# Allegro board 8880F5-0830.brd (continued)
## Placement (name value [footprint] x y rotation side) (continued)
NOREF#872  -  []  302.11 192.14 0 top
NOREF#873  -  []  166.06 175.58 90 top
NOREF#874  -  []  337.9 246.99 0 top
NOREF#875  -  []  210.86 242.18 90 top
NOREF#876  -  []  292.74 288.86 0 top
NOREF#877  -  []  215.96 248.49 0 top
NOREF#878  -  []  296.96 240.71 0 top
NOREF#879  -  []  240.83 194.63 0 top
NOREF#880  -  []  378.33 257.11 90 top
NOREF#881  -  []  300.36 237.06 0 top
NOREF#882  -  []  263.31 164.72 0 top
NOREF#883  -  []  313.94 286.96 90 top
NOREF#884  -  []  314.71 129.74 90 top
NOREF#885  -  []  209.23 191.22 90 top
NOREF#886  -  []  94.93 190.55 0 top
NOREF#887  -  []  218.16 237.06 0 top
NOREF#888  -  []  352.25 241.05 90 top
NOREF#889  -  []  412.37 265.37 0 top
NOREF#890  -  []  167.7 241.43 90 top
NOREF#891  -  []  230.43 254.01 0 top
NOREF#892  -  []  201.23 192.32 90 top
NOREF#893  -  []  209.08 256.4 90 top
NOREF#894  -  []  221.56 190.49 0 top
NOREF#895  -  []  462.06 291.28 90 top
NOREF#896  -  []  201.49 165.4 90 top
NOREF#897  -  []  209.49 162.1 90 top
NOREF#898  -  []  405.93 272.56 90 top
NOREF#899  -  []  303.84 288.86 0 top
NOREF#900  -  []  167.7 214 0 top
NOREF#901  -  []  231.15 219.63 90 top
NOREF#902  -  []  310.43 188.88 0 top
NOREF#903  -  []  397.8 163.19 90 top
NOREF#904  -  []  309.21 193.37 0 top
NOREF#905  -  []  121.9 231.22 0 top
NOREF#906  -  []  309.05 211.67 0 top
NOREF#907  -  []  310.43 253.37 90 top
NOREF#908  -  []  199.33 212.85 0 top
NOREF#909  -  []  394 217.36 0 top
NOREF#910  -  []  182.82 175.58 90 top
NOREF#911  -  []  306.83 209.63 90 top
NOREF#912  -  []  334.29 265.56 0 top
NOREF#913  -  []  339.33 265.56 0 top
NOREF#914  -  []  390.53 188.15 0 top
NOREF#915  -  []  201.49 173.11 90 top
NOREF#916  -  []  319.33 176.03 0 top
NOREF#917  -  []  392.04 241.11 90 top
NOREF#918  -  []  273.95 147.38 90 top
NOREF#919  -  []  312.79 288.86 90 top
NOREF#920  -  []  119.7 231.22 0 top
NOREF#921  -  []  310.43 246.34 90 top
NOREF#922  -  []  330.51 288.86 0 top
NOREF#923  -  []  412.36 209.61 90 top
NOREF#924  -  []  122.19 214.79 0 top
NOREF#925  -  []  398.65 225.11 0 top
NOREF#926  -  []  369.38 257.11 0 top
NOREF#927  -  []  177.33 187.32 90 top
NOREF#928  -  []  108.01 195.15 0 top
NOREF#929  -  []  410.78 131.89 0 top
NOREF#930  -  []  330.73 204.35 90 top
NOREF#931  -  []  118.45 234.24 90 top
NOREF#932  -  []  304.65 211.67 0 top
NOREF#933  -  []  263.71 288.86 0 top
NOREF#934  -  []  408.37 258.64 90 top
NOREF#935  -  []  175.7 148.38 90 top
NOREF#936  -  []  262.36 223.82 90 top
NOREF#937  -  []  230.41 187.61 90 top
NOREF#938  -  []  247.57 205.86 90 top
NOREF#939  -  []  184.47 200.54 90 top
NOREF#940  -  []  211.11 173.86 90 top
NOREF#941  -  []  272.25 189.82 0 top
NOREF#942  -  []  128.21 178.64 0 top
NOREF#943  -  []  406.65 223.21 90 top
NOREF#944  -  []  273.09 288.41 90 top
NOREF#945  -  []  263.63 225.04 90 top
NOREF#946  -  []  296.81 275.94 0 top
NOREF#947  -  []  229.51 247.93 0 top
NOREF#948  -  []  108.01 222.33 0 top
NOREF#949  -  []  167.7 260.9 90 top
NOREF#950  -  []  400.24 198.08 90 top
NOREF#951  -  []  463.61 214.96 0 top
NOREF#952  -  []  167.7 159.65 0 top
NOREF#953  -  []  272.55 243.91 0 top
NOREF#954  -  []  326.17 131.69 90 top
NOREF#955  -  []  93.76 271.33 90 top
NOREF#956  -  []  259.65 204.65 90 top
NOREF#957  -  []  456.08 214.96 0 top
NOREF#958  -  []  449.99 174.46 0 top
NOREF#959  -  []  200.98 260.9 90 top
NOREF#960  -  []  167.7 247.18 90 top
NOREF#961  -  []  385.19 297.12 0 top
NOREF#962  -  []  311.15 219.63 90 top
NOREF#963  -  []  383.09 224.85 0 top
NOREF#964  -  []  167.7 173.11 0 top
NOREF#965  -  []  338.2 186.67 0 top
NOREF#966  -  []  211.11 146.93 90 top
NOREF#967  -  []  108.27 171.02 0 top
NOREF#968  -  []  253.4 265.56 0 top
NOREF#969  -  []  415.08 139.89 0 top
NOREF#970  -  []  334.29 265.56 90 top
NOREF#971  -  []  473.6 162.62 90 top
NOREF#972  -  []  200.98 255.15 90 top
NOREF#973  -  []  254.61 264.65 90 top
NOREF#974  -  []  302.49 296.86 0 top
NOREF#975  -  []  368.03 249.11 0 top
NOREF#976  -  []  175.8 201.79 90 top
NOREF#977  -  []  338.36 288.91 90 top
NOREF#978  -  []  310.43 186.34 90 top
NOREF#979  -  []  465.31 186.77 0 top
NOREF#980  -  []  308.36 262.16 45 top
NOREF#981  -  []  408.28 129.99 0 top
NOREF#982  -  []  230.73 187.93 0 top
NOREF#983  -  []  165.8 131.57 0 top
NOREF#984  -  []  309.51 243.41 0 top
NOREF#985  -  []  322.62 139.64 0 top
NOREF#986  -  []  122.19 247.3 90 top
NOREF#987  -  []  199.33 199.39 90 top
NOREF#988  -  []  295.96 248.49 0 top
NOREF#989  -  []  184.47 260.9 90 top
NOREF#990  -  []  419.22 257.37 90 top
NOREF#991  -  []  331.62 204.35 90 top
NOREF#992  -  []  354.08 286.96 90 top
NOREF#993  -  []  217.83 234.63 90 top
NOREF#994  -  []  272.24 181.05 90 top
NOREF#995  -  []  201.23 215.35 90 top
NOREF#996  -  []  381.74 281.11 0 top
NOREF#997  -  []  271.04 244.23 0 top
NOREF#998  -  []  246.23 173.13 0 top
NOREF#999  -  []  256.77 223.82 90 top
NOREF#1000  -  []  175.7 264.1 90 top
NOREF#1001  -  []  339.89 288.41 90 top
NOREF#1002  -  []  369.63 289.12 0 top
NOREF#1003  -  []  330.17 165.04 90 top
NOREF#1004  -  []  369.38 257.11 0 top
NOREF#1005  -  []  419.64 256.82 90 top
NOREF#1006  -  []  258.2 246.67 0 top
NOREF#1007  -  []  235.85 296.61 0 top
NOREF#1008  -  []  310.43 247.61 0 top
NOREF#1009  -  []  396.03 146.88 0 top
NOREF#1010  -  []  312.25 211.67 90 top
NOREF#1011  -  []  450.03 210.36 0 top
NOREF#1012  -  []  409.74 180.2 90 top
NOREF#1013  -  []  277.17 288.86 0 top
NOREF#1014  -  []  410.52 289.12 0 top
NOREF#1015  -  []  333.72 264.65 90 top
NOREF#1016  -  []  301.56 242.89 0 top
NOREF#1017  -  []  201.23 241.43 90 top
NOREF#1018  -  []  420.37 255.47 90 top
NOREF#1019  -  []  383.73 202.38 90 top
NOREF#1020  -  []  262.36 225.04 90 top
NOREF#1021  -  []  168.13 172.56 90 top
NOREF#1022  -  []  346.27 129.42 0 top
NOREF#1023  -  []  271.04 185.5 0 top
NOREF#1024  -  []  304.65 271.67 0 top
NOREF#1025  -  []  240.94 211.63 90 top
NOREF#1026  -  []  310.73 193.69 0 top
NOREF#1027  -  []  343.95 163.52 90 top
NOREF#1028  -  []  165.8 226.57 90 top
NOREF#1029  -  []  518.38 273.87 90 top
NOREF#1030  -  []  395.2 281.11 0 top
NOREF#1031  -  []  479.44 195.66 0 top
NOREF#1032  -  []  451.68 186.77 0 top
NOREF#1033  -  []  463.11 230.2 0 top
NOREF#1034  -  []  473.79 196.21 0 top
NOREF#1035  -  []  119.95 222.33 0 top
NOREF#1036  -  []  271.34 243.91 0 top
NOREF#1037  -  []  351.04 189.18 0 top
NOREF#1038  -  []  343.31 224.74 0 top
NOREF#1039  -  []  209.23 243.88 90 top
NOREF#1040  -  []  201.49 146.18 90 top
NOREF#1041  -  []  250.74 164.74 0 top
NOREF#1042  -  []  461.96 210.36 0 top
NOREF#1043  -  []  184.47 242.78 90 top
NOREF#1044  -  []  371.48 257.11 0 top
NOREF#1045  -  []  332.83 204.65 90 top
NOREF#1046  -  []  306.71 139.64 0 top
NOREF#1047  -  []  304.61 131.64 0 top
NOREF#1048  -  []  351.34 249.5 0 top
NOREF#1049  -  []  331.22 253.63 0 top
NOREF#1050  -  []  184.47 260.9 90 top
NOREF#1051  -  []  397.38 163.64 90 top
NOREF#1052  -  []  309.21 253.37 0 top
NOREF#1053  -  []  271.34 249.5 0 top
NOREF#1054  -  []  250.73 204.35 90 top
NOREF#1055  -  []  459.28 236.14 90 top
NOREF#1056  -  []  297.83 174.63 90 top
NOREF#1057  -  []  369.63 273.11 0 top
NOREF#1058  -  []  327.57 205.86 90 top
NOREF#1059  -  []  184.47 241.43 90 top
NOREF#1060  -  []  330.73 205.56 90 top
NOREF#1061  -  []  247.25 205.56 0 top
NOREF#1062  -  []  383.09 257.11 0 top
NOREF#1063  -  []  263.31 224.72 0 top
NOREF#1064  -  []  387.8 210.63 90 top
NOREF#1065  -  []  340.83 174.63 90 top
NOREF#1066  -  []  250.18 242.88 0 top
NOREF#1067  -  []  272.25 182.96 0 top
NOREF#1068  -  []  230.73 253.69 0 top
NOREF#1069  -  []  310.73 189.2 0 top
NOREF#1070  -  []  320.83 194.63 0 top
NOREF#1071  -  []  328.62 290.13 90 top
NOREF#1072  -  []  461.96 174.55 0 top
NOREF#1073  -  []  408.88 133.16 90 top
NOREF#1074  -  []  401.87 194.18 90 top
NOREF#1075  -  []  100.98 195.15 0 top
NOREF#1076  -  []  387.08 171.64 0 top
NOREF#1077  -  []  331.38 164.74 90 top
NOREF#1078  -  []  230.43 189.52 0 top
NOREF#1079  -  []  413.75 171.64 0 top
NOREF#1080  -  []  118.99 166.5 90 top
NOREF#1081  -  []  396.03 163.64 0 top
NOREF#1082  -  []  351.34 243.91 0 top
NOREF#1083  -  []  272.25 245.5 0 top
NOREF#1084  -  []  418.12 289.12 0 top
NOREF#1085  -  []  339.65 204.65 90 top
NOREF#1086  -  []  261.16 135.74 90 top
NOREF#1087  -  []  422.95 163.69 90 top
NOREF#1088  -  []  167.7 176.66 90 top
NOREF#1089  -  []  330.17 225.04 90 top
NOREF#1090  -  []  453.88 239.34 0 top
NOREF#1091  -  []  379.52 171.39 0 top
NOREF#1092  -  []  331.05 204.65 90 top
NOREF#1093  -  []  215.96 237.06 0 top
NOREF#1094  -  []  405.93 240.66 90 top
NOREF#1095  -  []  314.55 286.96 0 top
NOREF#1096  -  []  352.25 185.5 0 top
NOREF#1097  -  []  259.88 288.41 90 top
NOREF#1098  -  []  376.15 192.88 90 top
NOREF#1099  -  []  379.48 255.21 90 top
NOREF#1100  -  []  119.95 187.53 0 top
NOREF#1101  -  []  184.47 165.4 90 top
NOREF#1102  -  []  242.23 173.13 90 top
NOREF#1103  -  []  376.98 241.11 0 top
NOREF#1104  -  []  351.04 245.5 0 top
NOREF#1105  -  []  192.57 228.97 90 top
NOREF#1106  -  []  311.15 159.63 90 top
NOREF#1107  -  []  336.77 223.82 90 top
NOREF#1108  -  []  351.04 185.5 0 top
NOREF#1109  -  []  230.43 248.88 90 top
NOREF#1110  -  []  410.27 257.37 0 top
NOREF#1111  -  []  201.49 146.18 0 top
NOREF#1112  -  []  168.69 292.55 90 top
NOREF#1113  -  []  106.76 210.11 90 top
NOREF#1114  -  []  396.55 257.37 0 top
NOREF#1115  -  []  300.36 188.49 0 top
NOREF#1116  -  []  331.62 265.56 0 top
NOREF#1117  -  []  201.23 244.98 90 top
NOREF#1118  -  []  385.93 161.74 0 top
NOREF#1119  -  []  333.33 241.33 90 top
NOREF#1120  -  []  310.73 187.93 0 top
NOREF#1121  -  []  209.33 187.82 90 top
NOREF#1122  -  []  410.84 180.15 90 top
NOREF#1123  -  []  310.73 253.69 0 top
NOREF#1124  -  []  385.19 232.85 0 top
NOREF#1125  -  []  387.08 154.88 0 top
NOREF#1126  -  []  229.21 248.88 0 top
NOREF#1127  -  []  230.73 189.2 0 top
NOREF#1128  -  []  251.06 225.04 90 top
NOREF#1129  -  []  275.3 155.38 0 top
NOREF#1130  -  []  471.21 168.33 90 top
NOREF#1131  -  []  485.36 259.9 90 top
NOREF#1132  -  []  419.65 256.92 90 top
NOREF#1133  -  []  252.83 265.86 90 top
NOREF#1134  -  []  284.77 288.86 0 top
NOREF#1135  -  []  390.53 163.64 0 top
NOREF#1136  -  []  333.4 205.55 0 top
NOREF#1137  -  []  369.38 241.11 0 top
NOREF#1138  -  []  259.45 288.86 90 top
NOREF#1139  -  []  415.61 179.97 90 top
NOREF#1140  -  []  379.73 271.21 90 top
NOREF#1141  -  []  271.56 134.74 90 top
NOREF#1142  -  []  165.8 185.42 90 top
NOREF#1143  -  []  343.98 288.86 0 top
NOREF#1144  -  []  232.25 211.67 90 top
NOREF#1145  -  []  259.88 288.31 90 top
NOREF#1146  -  []  303.84 288.86 0 top
NOREF#1147  -  []  400.91 207.71 0 top
NOREF#1148  -  []  352.24 243.59 90 top
NOREF#1149  -  []  302.11 129.74 0 top
NOREF#1150  -  []  315.16 290.13 90 top
NOREF#1151  -  []  327.7 131.19 90 top
NOREF#1152  -  []  167.7 204.09 90 top
NOREF#1153  -  []  406.65 287.22 90 top
NOREF#1154  -  []  36.1 129.71 90 top
NOREF#1155  -  []  398.65 289.12 0 top
NOREF#1156  -  []  406.94 131.34 90 top
NOREF#1157  -  []  371.73 297.12 0 top
NOREF#1158  -  []  175.7 141.67 90 top
NOREF#1159  -  []  392.47 288.67 90 top
NOREF#1160  -  []  200.98 260.9 90 top
NOREF#1161  -  []  471.21 219.38 0 top
NOREF#1162  -  []  295.19 271.65 90 top
NOREF#1163  -  []  398.65 273.11 0 top
NOREF#1164  -  []  331.62 205.55 0 top
NOREF#1165  -  []  312.21 131.64 0 top
NOREF#1166  -  []  319.33 183.63 90 top
NOREF#1167  -  []  418.38 131.89 0 top
NOREF#1168  -  []  272.25 241.05 90 top
NOREF#1169  -  []  264.29 280.1 0 top
NOREF#1170  -  []  230.73 183.41 0 top
NOREF#1171  -  []  301.56 179.06 0 top
NOREF#1172  -  []  408.63 290.39 90 top
NOREF#1173  -  []  249.6 223.52 90 top
NOREF#1174  -  []  201.21 276.04 90 top
NOREF#1175  -  []  184.47 219.75 90 top
NOREF#1176  -  []  472.86 174.55 90 top
NOREF#1177  -  []  451.68 239.34 0 top
NOREF#1178  -  []  259.33 205.55 0 top
NOREF#1179  -  []  409.43 139.89 0 top
NOREF#1180  -  []  200.98 255.15 0 top
NOREF#1181  -  []  167.7 233.47 90 top
NOREF#1182  -  []  120.24 171.1 0 top
NOREF#1183  -  []  115.61 219.13 90 top
NOREF#1184  -  []  396.28 146.93 90 top
NOREF#1185  -  []  242.23 233.13 0 top
NOREF#1186  -  []  167.7 247.18 90 top
NOREF#1187  -  []  310.43 246.34 0 top
NOREF#1188  -  []  376.23 209.11 0 top
NOREF#1189  -  []  393.19 271.21 90 top
NOREF#1190  -  []  249.13 140.14 0 top
NOREF#1191  -  []  330.49 163.52 90 top
NOREF#1192  -  []  167.7 132.72 90 top
NOREF#1193  -  []  182.82 216.47 90 top
NOREF#1194  -  []  248.61 290.13 90 top
NOREF#1195  -  []  230.41 253.37 90 top
NOREF#1196  -  []  331.38 224.74 90 top
NOREF#1197  -  []  175.7 216.45 90 top
NOREF#1198  -  []  223.56 185.29 90 top
NOREF#1199  -  []  352.25 182.32 90 top
NOREF#1200  -  []  253.4 205.55 0 top
NOREF#1201  -  []  295.96 177.06 0 top
NOREF#1202  -  []  110.21 195.15 0 top
NOREF#1203  -  []  118.7 190.55 90 top
NOREF#1204  -  []  475.04 239.09 0 top
NOREF#1205  -  []  216.96 180.71 0 top
NOREF#1206  -  []  343.31 164.74 0 top
NOREF#1207  -  []  250.73 265.56 0 top
NOREF#1208  -  []  390.53 146.88 0 top
NOREF#1209  -  []  167.7 219.75 90 top
NOREF#1210  -  []  201.21 273.5 90 top
NOREF#1211  -  []  177.33 160.4 90 top
NOREF#1212  -  []  456.08 230.2 0 top
NOREF#1213  -  []  118.96 179.19 0 top
NOREF#1214  -  []  397.57 131.89 0 top
NOREF#1215  -  []  390.53 180.15 0 top
NOREF#1216  -  []  328.42 129.74 90 top
NOREF#1217  -  []  396.55 289.12 0 top
NOREF#1218  -  []  250.73 265.55 0 top
NOREF#1219  -  []  262.04 224.74 0 top
NOREF#1220  -  []  352.24 183.59 90 top
NOREF#1221  -  []  184.47 229.07 90 top
NOREF#1222  -  []  116.27 178.64 0 top
NOREF#1223  -  []  318.32 131.64 0 top
NOREF#1224  -  []  201.49 178.86 90 top
NOREF#1225  -  []  313.22 288.41 90 top
NOREF#1226  -  []  254.29 264.35 90 top
NOREF#1227  -  []  277.5 155.38 0 top
NOREF#1228  -  []  407.77 255.47 0 top
NOREF#1229  -  []  353.35 288.41 90 top
NOREF#1230  -  []  256.77 225.04 90 top
NOREF#1231  -  []  303.15 211.32 90 top
NOREF#1232  -  []  223.56 173.86 90 top
NOREF#1233  -  []  401.89 180.15 0 top
NOREF#1234  -  []  167.7 173.11 90 top
NOREF#1235  -  []  352.25 249.82 0 top
NOREF#1236  -  []  251.62 265.56 90 top
NOREF#1237  -  []  251.62 204.35 90 top
NOREF#1238  -  []  317.66 164.74 0 top
NOREF#1239  -  []  251.54 192.73 90 top
NOREF#1240  -  []  309.51 247.93 0 top
NOREF#1241  -  []  192.47 218.65 90 top
NOREF#1242  -  []  459.28 168.33 90 top
NOREF#1243  -  []  175.7 230.17 90 top
NOREF#1244  -  []  272.55 241.37 0 top
NOREF#1245  -  []  385.32 178.25 90 top
NOREF#1246  -  []  403.41 209.61 0 top
NOREF#1247  -  []  384.59 179.6 90 top
NOREF#1248  -  []  118.96 174.04 90 top
NOREF#1249  -  []  511.59 259.9 90 top
NOREF#1250  -  []  184.47 241.43 0 top
NOREF#1251  -  []  546.67 300.44 90 top
NOREF#1252  -  []  333.72 265.86 90 top
NOREF#1253  -  []  373.87 188.15 0 top
NOREF#1254  -  []  290.11 280.1 0 top
NOREF#1255  -  []  106.76 222.88 0 top
NOREF#1256  -  []  381.86 129.99 0 top
NOREF#1257  -  []  475.36 127 90 top
NOREF#1258  -  []  423.45 146.93 90 top
NOREF#1259  -  []  272.55 182.64 0 top
NOREF#1260  -  []  396.55 225.11 0 top
NOREF#1261  -  []  260.74 143.19 0 top
NOREF#1262  -  []  395.07 129.99 0 top
NOREF#1263  -  []  273.95 155.38 0 top
NOREF#1264  -  []  184.47 256.5 90 top
NOREF#1265  -  []  230.43 253.37 90 top
NOREF#1266  -  []  471.21 175.95 0 top
NOREF#1267  -  []  247.57 204.65 90 top
NOREF#1268  -  []  299.59 288.86 90 top
NOREF#1269  -  []  331.06 165.04 90 top
NOREF#1270  -  []  246.23 233.13 0 top
NOREF#1271  -  []  418.63 131.94 90 top
NOREF#1272  -  []  292.74 296.86 0 top
NOREF#1273  -  []  351.04 242.96 0 top
NOREF#1274  -  []  304.61 131.64 0 top
NOREF#1275  -  []  192.47 177.76 90 top
NOREF#1276  -  []  419.4 171.64 0 top
NOREF#1277  -  []  459.28 183.57 90 top
NOREF#1278  -  []  332.83 205.86 90 top
NOREF#1279  -  []  319.33 176.03 90 top
NOREF#1280  -  []  330.49 223.52 90 top
NOREF#1281  -  []  239.33 183.63 90 top
NOREF#1282  -  []  261.82 290.13 90 top
NOREF#1283  -  []  272.55 185.18 0 top
NOREF#1284  -  []  225.83 264.31 0 top
NOREF#1285  -  []  165.8 254 90 top
NOREF#1286  -  []  192.47 236.67 90 top
NOREF#1287  -  []  112.41 195.15 0 top
NOREF#1288  -  []  367.48 258.38 90 top
NOREF#1289  -  []  306.27 216.63 90 top
NOREF#1290  -  []  182.82 162.12 90 top
NOREF#1291  -  []  308.36 202.16 45 top
NOREF#1292  -  []  367.48 225.87 90 top
NOREF#1293  -  []  375.22 180.15 0 top
NOREF#1294  -  []  368.28 281.11 0 top
NOREF#1295  -  []  461.86 187.32 0 top
NOREF#1296  -  []  300.11 273.24 90 top
NOREF#1297  -  []  240.83 254.63 0 top
NOREF#1298  -  []  208.98 259.8 90 top
NOREF#1299  -  []  276.4 147.38 0 top
NOREF#1300  -  []  122.15 195.15 0 top
NOREF#1301  -  []  201.49 151.93 90 top
NOREF#1302  -  []  366.88 255.21 0 top
NOREF#1303  -  []  251.38 164.74 90 top
NOREF#1304  -  []  122.15 222.33 0 top
NOREF#1305  -  []  270.04 135.24 90 top
NOREF#1306  -  []  409.17 281.37 0 top
NOREF#1307  -  []  411.01 209.61 0 top
NOREF#1308  -  []  201.23 200.54 0 top
NOREF#1309  -  []  403.99 171.64 0 top
NOREF#1310  -  []  467.51 186.77 0 top
NOREF#1311  -  []  346.27 130.77 90 top
NOREF#1312  -  []  165.8 240.28 90 top
NOREF#1313  -  []  309.12 154.05 0 top
NOREF#1314  -  []  209.23 250.38 90 top
NOREF#1315  -  []  371.48 249.11 0 top
NOREF#1316  -  []  341.48 286.96 0 top
NOREF#1317  -  []  184.47 214 0 top
NOREF#1318  -  []  230.41 193.37 90 top
NOREF#1319  -  []  339.65 264.65 90 top
NOREF#1320  -  []  305.83 204.31 0 top
NOREF#1321  -  []  386.53 164.91 90 top
NOREF#1322  -  []  184.47 147.28 90 top
NOREF#1323  -  []  119.7 238.84 0 top
NOREF#1324  -  []  248.21 132.69 90 top
NOREF#1325  -  []  403.99 163.64 0 top
NOREF#1326  -  []  352.25 182.96 0 top
NOREF#1327  -  []  351.34 185.18 0 top
NOREF#1328  -  []  397.3 209.36 0 top
NOREF#1329  -  []  309.21 186.34 0 top
NOREF#1330  -  []  263.2 172.26 90 top
NOREF#1331  -  []  236.27 289.16 90 top
NOREF#1332  -  []  396.55 289.12 0 top
NOREF#1333  -  []  251.22 253.63 0 top
NOREF#1334  -  []  354.27 131.87 90 top
NOREF#1335  -  []  247.25 265.56 90 top
NOREF#1336  -  []  263.95 163.52 90 top
NOREF#1337  -  []  309.21 248.88 0 top
NOREF#1338  -  []  259.33 264.35 90 top
NOREF#1339  -  []  251.86 192.43 90 top
NOREF#1340  -  []  263.14 270.2 90 top
NOREF#1341  -  []  352.25 245.5 0 top
NOREF#1342  -  []  230.43 248.88 90 top
NOREF#1343  -  []  312.25 271.67 90 top
NOREF#1344  -  []  226.83 209.63 90 top
NOREF#1345  -  []  106.11 234.24 0 top
NOREF#1346  -  []  118.7 195.7 0 top
NOREF#1347  -  []  215.96 177.06 0 top
NOREF#1348  -  []  275.28 290.13 90 top
NOREF#1349  -  []  290.11 280.1 0 top
NOREF#1350  -  []  396.55 273.11 0 top
NOREF#1351  -  []  449.99 174.46 0 top
NOREF#1352  -  []  327.15 286.96 90 top
NOREF#1353  -  []  317.05 288.86 0 top
NOREF#1354  -  []  259.33 205.56 0 top
NOREF#1355  -  []  272.24 183.59 90 top
NOREF#1356  -  []  394.66 258.64 90 top
NOREF#1357  -  []  343.63 223.82 90 top
NOREF#1358  -  []  317.83 197.63 0 top
NOREF#1359  -  []  98.78 195.15 0 top
NOREF#1360  -  []  317.66 164.72 0 top
NOREF#1361  -  []  471.21 168.33 0 top
NOREF#1362  -  []  315.7 296.86 0 top
NOREF#1363  -  []  404.15 273.11 0 top
NOREF#1364  -  []  251.38 223.52 90 top
NOREF#1365  -  []  192.47 246.08 90 top
NOREF#1366  -  []  219.81 213.69 90 top
NOREF#1367  -  []  332.61 288.86 0 top
NOREF#1368  -  []  423.2 146.88 0 top
NOREF#1369  -  []  242.23 173.13 0 top
NOREF#1370  -  []  230.73 193.69 0 top
NOREF#1371  -  []  272.25 183.59 90 top
NOREF#1372  -  []  106.76 215.26 0 top
NOREF#1373  -  []  230.41 186.34 90 top
NOREF#1374  -  []  209.49 175.56 90 top
NOREF#1375  -  []  383.09 241.11 0 top
NOREF#1376  -  []  342.08 290.13 90 top
NOREF#1377  -  []  333.4 264.35 90 top
NOREF#1378  -  []  108.01 214.71 0 top
NOREF#1379  -  []  184.47 217.55 90 top
NOREF#1380  -  []  112.41 222.33 0 top
NOREF#1381  -  []  329.6 223.52 90 top
NOREF#1382  -  []  220.36 237.06 0 top
NOREF#1383  -  []  388.43 180.15 0 top
NOREF#1384  -  []  192.47 250.38 90 top
NOREF#1385  -  []  385.36 194.18 90 top
NOREF#1386  -  []  247.25 205.55 0 top
NOREF#1387  -  []  201.49 163.2 90 top
NOREF#1388  -  []  397.38 146.88 90 top
NOREF#1389  -  []  226.85 211.67 0 top
NOREF#1390  -  []  298.13 274.06 90 top
NOREF#1391  -  []  338.11 288.86 0 top
NOREF#1392  -  []  373.32 164.66 90 top
NOREF#1393  -  []  413.96 182.44 90 top
NOREF#1394  -  []  383.09 257.11 0 top
NOREF#1395  -  []  451.68 171.53 0 top
NOREF#1396  -  []  35.83 128.17 90 top
NOREF#1397  -  []  410.27 257.37 0 top
NOREF#1398  -  []  390.53 171.64 0 top
NOREF#1399  -  []  252.43 132.14 0 top
NOREF#1400  -  []  383.01 139.89 0 top
NOREF#1401  -  []  250.74 164.72 0 top
NOREF#1402  -  []  259.65 265.86 90 top
NOREF#1403  -  []  246.63 142.04 0 top
NOREF#1404  -  []  250.74 224.72 0 top
NOREF#1405  -  []  318.3 163.52 90 top
NOREF#1406  -  []  314.33 228.13 90 top
NOREF#1407  -  []  108.01 195.15 0 top
NOREF#1408  -  []  238.3 224.74 90 top
NOREF#1409  -  []  105.93 204.27 90 top
NOREF#1410  -  []  409.17 249.11 0 top
NOREF#1411  -  []  175.7 162.1 90 top
NOREF#1412  -  []  201.23 206.29 90 top
NOREF#1413  -  []  103.93 235.64 0 top
NOREF#1414  -  []  339.33 265.56 90 top
NOREF#1415  -  []  251.38 224.74 90 top
NOREF#1416  -  []  398.53 178.25 90 top
NOREF#1417  -  []  172.08 275.14 90 top
NOREF#1418  -  []  310.43 243.09 90 top
NOREF#1419  -  []  449.99 217.9 0 top
NOREF#1420  -  []  192.47 243.88 90 top
NOREF#1421  -  []  271.31 288.86 0 top
NOREF#1422  -  []  182.57 171.96 0 top
NOREF#1423  -  []  272.25 243.59 90 top
NOREF#1424  -  []  272.55 183.91 0 top
NOREF#1425  -  []  271.34 185.18 0 top
NOREF#1426  -  []  112.05 246.78 90 top
NOREF#1427  -  []  263.31 164.74 0 top
NOREF#1428  -  []  450.03 191.31 0 top
NOREF#1429  -  []  461.86 187.32 0 top
NOREF#1430  -  []  238.3 163.52 90 top
NOREF#1431  -  []  327.89 204.35 90 top
NOREF#1432  -  []  275.82 296.86 0 top
NOREF#1433  -  []  256.45 224.72 0 top
NOREF#1434  -  []  201.23 229.07 90 top
NOREF#1435  -  []  117.33 247.35 90 top
NOREF#1436  -  []  192.47 232.37 90 top
NOREF#1437  -  []  230.43 188.88 90 top
NOREF#1438  -  []  309.21 246.34 0 top
NOREF#1439  -  []  229.21 183.09 0 top
NOREF#1440  -  []  252.51 204.35 90 top
NOREF#1441  -  []  418.12 257.42 90 top
NOREF#1442  -  []  330.17 223.82 90 top
NOREF#1443  -  []  210.86 214.75 90 top
NOREF#1444  -  []  98.53 238.84 0 top
NOREF#1445  -  []  388.35 217.36 0 top
NOREF#1446  -  []  327.27 131.64 90 top
NOREF#1447  -  []  93.76 287.84 90 top
NOREF#1448  -  []  465.81 222.58 0 top
NOREF#1449  -  []  383.09 241.11 0 top
NOREF#1450  -  []  263.63 223.82 90 top
NOREF#1451  -  []  390.53 154.88 0 top
NOREF#1452  -  []  283.21 270.2 90 top
NOREF#1453  -  []  192.57 242.68 90 top
NOREF#1454  -  []  352.24 181.05 90 top
NOREF#1455  -  []  168.13 159.1 90 top
NOREF#1456  -  []  250.17 223.82 90 top
NOREF#1457  -  []  371.48 232.6 0 top
NOREF#1458  -  []  528.1 257.36 90 top
NOREF#1459  -  []  177.33 146.68 90 top
NOREF#1460  -  []  184.89 172.56 90 top
NOREF#1461  -  []  310.73 193.69 0 top
NOREF#1462  -  []  411.99 178.25 90 top
NOREF#1463  -  []  404.15 257.37 0 top
NOREF#1464  -  []  209.23 205.19 90 top
NOREF#1465  -  []  374.34 210.38 90 top
NOREF#1466  -  []  337.9 246.35 90 top
NOREF#1467  -  []  405.93 288.57 90 top
NOREF#1468  -  []  475.04 195.66 0 top
NOREF#1469  -  []  199.84 162.12 90 top
NOREF#1470  -  []  559.43 297.18 90 top
NOREF#1471  -  []  310.43 188.88 90 top
NOREF#1472  -  []  201.66 186.02 90 top
NOREF#1473  -  []  351.04 244.23 0 top
NOREF#1474  -  []  453.88 230.2 0 top
NOREF#1475  -  []  461.86 225.6 90 top
NOREF#1476  -  []  501.87 276.41 90 top
NOREF#1477  -  []  199.08 254 90 top
NOREF#1478  -  []  166.06 162.12 90 top
NOREF#1479  -  []  201.23 227.72 0 top
NOREF#1480  -  []  192.57 160.9 90 top
NOREF#1481  -  []  333.72 205.86 90 top
NOREF#1482  -  []  184.47 247.18 90 top
NOREF#1483  -  []  199.59 158.5 90 top
NOREF#1484  -  []  298.16 237.06 0 top
NOREF#1485  -  []  378.75 224.15 90 top
NOREF#1486  -  []  396.55 273.11 0 top
NOREF#1487  -  []  339.33 265.55 0 top
NOREF#1488  -  []  410.52 241.11 0 top
NOREF#1489  -  []  450.03 182.17 0 top
NOREF#1490  -  []  118.45 231.77 0 top
NOREF#1491  -  []  331.05 265.86 90 top
NOREF#1492  -  []  199.59 203.01 90 top
NOREF#1493  -  []  352.24 242.32 90 top
NOREF#1494  -  []  327.25 265.56 90 top
NOREF#1495  -  []  247.57 264.65 90 top
NOREF#1496  -  []  118.7 222.88 0 top
NOREF#1497  -  []  410.52 273.37 0 top
NOREF#1498  -  []  390.94 241.16 90 top
NOREF#1499  -  []  229.21 186.34 0 top
NOREF#1500  -  []  209.59 147.43 90 top
NOREF#1501  -  []  334.29 264.35 90 top
NOREF#1502  -  []  468.01 179.15 0 top
NOREF#1503  -  []  351.58 288.86 0 top
NOREF#1504  -  []  353.35 288.31 90 top
NOREF#1505  -  []  410.52 273.37 0 top
NOREF#1506  -  []  234.7 286.71 90 top
NOREF#1507  -  []  108.27 171.02 0 top
NOREF#1508  -  []  383.09 289.12 0 top
NOREF#1509  -  []  182.82 148.4 90 top
NOREF#1510  -  []  250.73 264.35 90 top
NOREF#1511  -  []  167.7 233.47 90 top
NOREF#1512  -  []  313.22 288.31 90 top
NOREF#1513  -  []  409.74 146.88 0 top
NOREF#1514  -  []  121.9 238.84 0 top
NOREF#1515  -  []  249.85 164.74 0 top
NOREF#1516  -  []  192.47 150.58 90 top
NOREF#1517  -  []  406.95 131.44 90 top
NOREF#1518  -  []  254.61 205.86 90 top
NOREF#1519  -  []  268.94 272.1 0 top
NOREF#1520  -  []  165.8 171.96 90 top
NOREF#1521  -  []  241.6 296.61 0 top
NOREF#1522  -  []  420.62 287.22 90 top
NOREF#1523  -  []  352.55 182.64 0 top
NOREF#1524  -  []  124.35 222.33 0 top
NOREF#1525  -  []  167.7 219.75 90 top
NOREF#1526  -  []  184.47 233.47 90 top
NOREF#1527  -  []  230.43 253.37 90 top
NOREF#1528  -  []  209.23 209.49 90 top
NOREF#1529  -  []  310.43 248.88 0 top
NOREF#1530  -  []  380.59 287.22 0 top
NOREF#1531  -  []  106.29 174.19 90 top
NOREF#1532  -  []  352.55 249.5 0 top
NOREF#1533  -  []  326.23 173.13 0 top
NOREF#1534  -  []  471.11 186.77 0 top
NOREF#1535  -  []  372.72 178.25 0 top
NOREF#1536  -  []  182.57 144.78 90 top
NOREF#1537  -  []  303.26 139.64 0 top
NOREF#1538  -  []  192.47 209.49 90 top
NOREF#1539  -  []  473.79 234.49 90 top
NOREF#1540  -  []  339.65 205.86 90 top
NOREF#1541  -  []  328.01 286.96 0 top
NOREF#1542  -  []  377.23 289.12 0 top
NOREF#1543  -  []  390.34 192.28 90 top
NOREF#1544  -  []  392.24 199.18 90 top
NOREF#1545  -  []  485.36 257.36 90 top
NOREF#1546  -  []  342.36 225.04 90 top
NOREF#1547  -  []  378.58 273.11 90 top
NOREF#1548  -  []  409.99 146.93 90 top
NOREF#1549  -  []  406.65 239.21 90 top
NOREF#1550  -  []  272.66 288.86 90 top
NOREF#1551  -  []  239.33 243.63 90 top
NOREF#1552  -  []  306.92 154.05 0 top
NOREF#1553  -  []  394.66 226.38 90 top
NOREF#1554  -  []  343.31 164.72 0 top
NOREF#1555  -  []  329.16 296.86 0 top
NOREF#1556  -  []  450.03 234.74 0 top
NOREF#1557  -  []  368.03 265.11 0 top
NOREF#1558  -  []  298.16 188.49 0 top
NOREF#1559  -  []  405.93 272.66 90 top
NOREF#1560  -  []  339.97 204.35 90 top
NOREF#1561  -  []  272.55 245.18 0 top
NOREF#1562  -  []  351.04 182.96 0 top
NOREF#1563  -  []  351.34 182.64 0 top
NOREF#1564  -  []  379 272.56 90 top
NOREF#1565  -  []  115.61 191.95 90 top
NOREF#1566  -  []  450.03 166.93 0 top
NOREF#1567  -  []  327.25 205.55 0 top
NOREF#1568  -  []  383.07 163.44 90 top
NOREF#1569  -  []  127.84 167.9 90 top
NOREF#1570  -  []  184.47 192.32 90 top
NOREF#1571  -  []  400.24 195.88 90 top
NOREF#1572  -  []  463.61 222.58 0 top
NOREF#1573  -  []  400.85 233.11 0 top
NOREF#1574  -  []  249.28 223.82 90 top
NOREF#1575  -  []  332.51 265.56 90 top
NOREF#1576  -  []  310.83 224.63 0 top
NOREF#1577  -  []  382.82 163.39 0 top
NOREF#1578  -  []  310.73 253.69 0 top
NOREF#1579  -  []  184.47 219.75 90 top
NOREF#1580  -  []  216.96 252.14 0 top
NOREF#1581  -  []  201.23 200.54 90 top
NOREF#1582  -  []  396.55 241.11 0 top
NOREF#1583  -  []  221.56 231.46 0 top
NOREF#1584  -  []  381.74 297.12 0 top
NOREF#1585  -  []  339.33 205.55 0 top
NOREF#1586  -  []  219.76 297.18 0 top
NOREF#1587  -  []  412.79 209.06 90 top
NOREF#1588  -  []  459.28 192.71 90 top
NOREF#1589  -  []  184.47 151.68 90 top
NOREF#1590  -  []  379.01 272.66 90 top
NOREF#1591  -  []  119.95 222.33 0 top
NOREF#1592  -  []  306.85 211.67 0 top
NOREF#1593  -  []  296.96 252.14 0 top
NOREF#1594  -  []  342.68 224.74 90 top
NOREF#1595  -  []  343.98 288.86 0 top
NOREF#1596  -  []  412.62 273.37 0 top
NOREF#1597  -  []  221.56 250.49 0 top
NOREF#1598  -  []  118.45 226.62 90 top
NOREF#1599  -  []  495.08 274.77 90 top
NOREF#1600  -  []  175.7 195.52 90 top
NOREF#1601  -  []  107.02 171.57 0 top
NOREF#1602  -  []  286.55 288.31 90 top
NOREF#1603  -  []  352.55 189.5 0 top
NOREF#1604  -  []  337.09 163.52 90 top
NOREF#1605  -  []  337.09 223.52 90 top
NOREF#1606  -  []  266.74 272.1 0 top
NOREF#1607  -  []  367.13 287.22 0 top
NOREF#1608  -  []  115.36 235.64 90 top
NOREF#1609  -  []  184.47 190.12 90 top
NOREF#1610  -  []  201.23 233.47 90 top
NOREF#1611  -  []  93.76 290.38 90 top
NOREF#1612  -  []  107.02 174.04 90 top
NOREF#1613  -  []  386.33 207.21 90 top
NOREF#1614  -  []  453.84 222.5 0 top
NOREF#1615  -  []  75.98 271.33 90 top
NOREF#1616  -  []  244.8 288.61 0 top
NOREF#1617  -  []  112.16 238.84 0 top
NOREF#1618  -  []  127.7 238.84 0 top
NOREF#1619  -  []  310.43 248.88 90 top
NOREF#1620  -  []  284.77 146.93 90 top
NOREF#1621  -  []  412.62 281.37 0 top
NOREF#1622  -  []  257.09 164.74 90 top
NOREF#1623  -  []  393.31 131.89 90 top
NOREF#1624  -  []  418.37 273.42 90 top
NOREF#1625  -  []  405.5 257.37 90 top
NOREF#1626  -  []  257.9 186.99 0 top
NOREF#1627  -  []  552.76 299.72 0 top
NOREF#1628  -  []  229.21 243.09 0 top
NOREF#1629  -  []  251.22 193.63 0 top
NOREF#1630  -  []  341.63 255.43 90 top
NOREF#1631  -  []  339.33 204.35 90 top
NOREF#1632  -  []  383.09 273.11 0 top
NOREF#1633  -  []  338.2 246.67 0 top
NOREF#1634  -  []  293.31 272.1 0 top
NOREF#1635  -  []  343.31 224.72 0 top
NOREF#1636  -  []  209.33 242.68 90 top
NOREF#1637  -  []  388.43 146.88 0 top
NOREF#1638  -  []  115.87 167.82 90 top
NOREF#1639  -  []  339.89 288.31 90 top
NOREF#1640  -  []  371.73 273.11 0 top
NOREF#1641  -  []  373.32 181.42 90 top
NOREF#1642  -  []  482.64 235.89 90 top
NOREF#1643  -  []  310.43 189.52 0 top
NOREF#1644  -  []  385.18 209.11 90 top
NOREF#1645  -  []  383.83 194.68 90 top
NOREF#1646  -  []  201.91 172.56 90 top
NOREF#1647  -  []  423.71 181.22 90 top
NOREF#1648  -  []  260.29 136.46 90 top
NOREF#1649  -  []  232.25 271.67 90 top
NOREF#1650  -  []  318.45 257.01 0 top
NOREF#1651  -  []  461.96 166.93 0 top
NOREF#1652  -  []  257.09 224.74 90 top
NOREF#1653  -  []  107.76 238.84 0 top
NOREF#1654  -  []  83.77 247.51 90 top
NOREF#1655  -  []  238.3 164.74 90 top
NOREF#1656  -  []  165.8 158.5 90 top
NOREF#1657  -  []  254.29 265.55 0 top
NOREF#1658  -  []  184.47 231.27 90 top
NOREF#1659  -  []  184.89 159.1 90 top
NOREF#1660  -  []  230.73 246.66 0 top
NOREF#1661  -  []  373.93 297.12 0 top
NOREF#1662  -  []  409.17 297.12 0 top
NOREF#1663  -  []  451.68 214.96 0 top
NOREF#1664  -  []  400.85 297.12 0 top
NOREF#1665  -  []  320.42 131.64 0 top
NOREF#1666  -  []  215.96 188.49 0 top
NOREF#1667  -  []  230.73 193.69 0 top
NOREF#1668  -  []  93.76 273.87 90 top
NOREF#1669  -  []  511.59 293.82 90 top
NOREF#1670  -  []  451.68 214.96 0 top
NOREF#1671  -  []  272.24 189.18 90 top
NOREF#1672  -  []  75.98 290.38 90 top
NOREF#1673  -  []  340.83 234.63 90 top
NOREF#1674  -  []  226.83 269.63 90 top
NOREF#1675  -  []  483.04 195.66 0 top
NOREF#1676  -  []  312.67 146.1 90 top
NOREF#1677  -  []  106.18 160.58 90 top
NOREF#1678  -  []  303.47 154.05 0 top
NOREF#1679  -  []  470.79 128.27 0 top
NOREF#1680  -  []  248.96 164.72 0 top
NOREF#1681  -  []  165.8 171.96 0 top
NOREF#1682  -  []  230.43 194.01 0 top
NOREF#1683  -  []  194.09 187.32 90 top
NOREF#1684  -  []  301.34 286.96 0 top
NOREF#1685  -  []  369.38 224.6 0 top
NOREF#1686  -  []  468.01 214.96 0 top
NOREF#1687  -  []  237.57 269.63 90 top
NOREF#1688  -  []  216.96 192.14 0 top
NOREF#1689  -  []  375.22 180.15 0 top
NOREF#1690  -  []  413.1 144.98 0 top
NOREF#1691  -  []  167.7 132.72 0 top
NOREF#1692  -  []  412.6 161.74 0 top
NOREF#1693  -  []  310.73 189.2 0 top
NOREF#1694  -  []  209.49 148.63 90 top
NOREF#1695  -  []  331.94 264.65 90 top
NOREF#1696  -  []  397.8 179.6 90 top
NOREF#1697  -  []  405.5 289.12 90 top
NOREF#1698  -  []  297.71 216.09 0 top
NOREF#1699  -  []  330.73 205.55 0 top
NOREF#1700  -  []  306.92 146.05 0 top
NOREF#1701  -  []  331.38 163.52 90 top
NOREF#1702  -  []  310.43 253.37 0 top
NOREF#1703  -  []  300.74 286.96 90 top
NOREF#1704  -  []  271.34 249.5 0 top
NOREF#1705  -  []  399.39 178.25 0 top
NOREF#1706  -  []  273.24 272.1 0 top
NOREF#1707  -  []  396.28 163.69 90 top
NOREF#1708  -  []  182.57 158.5 90 top
NOREF#1709  -  []  175.7 236.67 90 top
NOREF#1710  -  []  424.55 146.88 90 top
NOREF#1711  -  []  343.2 232.26 90 top
NOREF#1712  -  []  306.27 156.63 90 top
NOREF#1713  -  []  184.47 151.68 90 top
NOREF#1714  -  []  321.82 167.13 90 top
NOREF#1715  -  []  239.33 236.03 0 top
NOREF#1716  -  []  319.33 236.03 0 top
NOREF#1717  -  []  397.8 146.33 90 top
NOREF#1718  -  []  405.5 273.11 90 top
NOREF#1719  -  []  259.33 205.55 0 top
NOREF#1720  -  []  252.51 265.56 0 top
NOREF#1721  -  []  220.36 188.49 0 top
NOREF#1722  -  []  331.62 264.35 90 top
NOREF#1723  -  []  226.44 294.64 90 top
NOREF#1724  -  []  415.61 179.97 0 top
NOREF#1725  -  []  177.33 242.18 90 top
NOREF#1726  -  []  111.54 287.84 90 top
NOREF#1727  -  []  320.94 151.63 90 top
NOREF#1728  -  []  396.55 241.11 0 top
NOREF#1729  -  []  103.93 235.64 90 top
NOREF#1730  -  []  387.08 188.15 0 top
NOREF#1731  -  []  258.1 288.86 0 top
NOREF#1732  -  []  393.19 239.21 90 top
NOREF#1733  -  []  303.56 233.86 90 top
NOREF#1734  -  []  168.69 290.01 90 top
NOREF#1735  -  []  334.29 205.55 0 top
NOREF#1736  -  []  317.05 288.86 0 top
NOREF#1737  -  []  254.8 296.86 0 top
NOREF#1738  -  []  127.3 228.02 90 top
NOREF#1739  -  []  167.7 186.57 0 top
NOREF#1740  -  []  406.19 171.64 0 top
NOREF#1741  -  []  175.7 205.19 90 top
NOREF#1742  -  []  184.47 215.35 90 top
NOREF#1743  -  []  177.33 133.47 90 top
NOREF#1744  -  []  279.7 155.38 0 top
NOREF#1745  -  []  402.14 146.88 0 top
NOREF#1746  -  []  117.26 190.55 90 top
NOREF#1747  -  []  107.02 179.19 0 top
NOREF#1748  -  []  201.66 213.45 90 top
NOREF#1749  -  []  263.19 135.19 0 top
NOREF#1750  -  []  336.45 164.74 0 top
NOREF#1751  -  []  453.84 179.06 0 top
NOREF#1752  -  []  263.83 171.63 90 top
NOREF#1753  -  []  317.98 163.82 90 top
NOREF#1754  -  []  399.99 181.42 90 top
NOREF#1755  -  []  468.01 171.53 0 top
NOREF#1756  -  []  273.59 272.15 90 top
NOREF#1757  -  []  400.24 202.38 90 top
NOREF#1758  -  []  249.85 224.74 0 top
NOREF#1759  -  []  230.43 186.34 0 top
NOREF#1760  -  []  223.15 271.32 90 top
NOREF#1761  -  []  234.7 298.51 0 top
NOREF#1762  -  []  118.33 271.33 90 top
NOREF#1763  -  []  226.27 156.63 90 top
NOREF#1764  -  []  165.8 212.85 90 top
NOREF#1765  -  []  254.61 265.86 90 top
NOREF#1766  -  []  331.06 225.04 90 top
NOREF#1767  -  []  165.8 131.57 90 top
NOREF#1768  -  []  279.27 288.86 0 top
NOREF#1769  -  []  248.33 247.93 0 top
NOREF#1770  -  []  201.21 292.55 90 top
NOREF#1771  -  []  238.45 257.01 0 top
NOREF#1772  -  []  385.93 144.98 0 top
NOREF#1773  -  []  175.8 147.18 90 top
NOREF#1774  -  []  259.65 264.65 90 top
NOREF#1775  -  []  383.73 195.88 90 top
NOREF#1776  -  []  473.79 191.06 90 top
NOREF#1777  -  []  397.8 179.7 90 top
NOREF#1778  -  []  404.24 154.88 0 top
NOREF#1779  -  []  412.88 139.89 0 top
NOREF#1780  -  []  93.02 247.21 90 top
NOREF#1781  -  []  404.15 289.12 0 top
NOREF#1782  -  []  167.7 149.48 90 top
NOREF#1783  -  []  201.23 186.57 90 top
NOREF#1784  -  []  264.29 143.19 0 top
NOREF#1785  -  []  383.09 273.11 0 top
NOREF#1786  -  []  240.5 288.61 0 top
NOREF#1787  -  []  462.06 274.77 90 top
NOREF#1788  -  []  247.25 204.35 90 top
NOREF#1789  -  []  369.63 273.11 0 top
NOREF#1790  -  []  382.47 133.16 90 top
NOREF#1791  -  []  229.21 253.37 0 top
NOREF#1792  -  []  271.04 181.69 0 top
NOREF#1793  -  []  388.43 180.15 0 top
NOREF#1794  -  []  383.83 209.11 0 top
NOREF#1795  -  []  461.96 166.93 0 top
NOREF#1796  -  []  290.64 288.86 0 top
NOREF#1797  -  []  310.43 248.88 90 top
NOREF#1798  -  []  302.71 132.91 90 top
NOREF#1799  -  []  272.55 242.64 0 top
NOREF#1800  -  []  295.96 188.49 0 top
NOREF#1801  -  []  465.45 276.41 90 top
NOREF#1802  -  []  411.26 163.09 90 top
NOREF#1803  -  []  265.64 280.1 0 top
NOREF#1804  -  []  222.11 240.71 0 top
NOREF#1805  -  []  261.63 233.83 90 top
NOREF#1806  -  []  297.41 213.24 0 top
NOREF#1807  -  []  411.26 179.7 90 top
NOREF#1808  -  []  192.57 174.36 90 top
NOREF#1809  -  []  460.93 210.36 90 top
NOREF#1810  -  []  330.18 242.88 0 top
NOREF#1811  -  []  303.56 173.86 90 top
NOREF#1812  -  []  257.9 246.99 0 top
NOREF#1813  -  []  310.41 248.88 90 top
NOREF#1814  -  []  379.01 288.67 90 top
NOREF#1815  -  []  293.66 272.15 90 top
NOREF#1816  -  []  463.61 222.58 0 top
NOREF#1817  -  []  381.74 249.11 0 top
NOREF#1818  -  []  168.13 254.6 90 top
NOREF#1819  -  []  310.43 254.01 0 top
NOREF#1820  -  []  165.8 185.42 0 top
NOREF#1821  -  []  451.68 195.91 0 top
NOREF#1822  -  []  465.45 273.87 90 top
NOREF#1823  -  []  378.75 240.66 90 top
NOREF#1824  -  []  201.49 174.46 90 top
NOREF#1825  -  []  256.45 164.74 0 top
NOREF#1826  -  []  331.38 223.52 90 top
NOREF#1827  -  []  96.33 238.84 0 top
NOREF#1828  -  []  257.9 246.35 90 top
NOREF#1829  -  []  344.62 131.89 90 top
NOREF#1830  -  []  209.33 201.79 90 top
NOREF#1831  -  []  182.57 185.42 90 top
NOREF#1832  -  []  218.13 274.06 0 top
NOREF#1833  -  []  266.49 143.19 0 top
NOREF#1834  -  []  381.2 258.38 90 top
NOREF#1835  -  []  468.85 259.9 90 top
NOREF#1836  -  []  478.57 293.82 90 top
NOREF#1837  -  []  192.47 189.02 90 top
NOREF#1838  -  []  218.13 274.06 90 top
NOREF#1839  -  []  167.7 206.29 90 top
NOREF#1840  -  []  391.8 217.36 0 top
NOREF#1841  -  []  392.04 289.12 90 top
NOREF#1842  -  []  182.57 185.42 0 top
NOREF#1843  -  []  116.01 222.33 0 top
NOREF#1844  -  []  369.38 241.11 0 top
NOREF#1845  -  []  261.63 173.83 90 top
NOREF#1846  -  []  192.47 264.1 90 top
NOREF#1847  -  []  283.91 273.37 90 top
NOREF#1848  -  []  217.71 216.09 0 top
NOREF#1849  -  []  279.27 296.86 0 top
NOREF#1850  -  []  220.36 248.49 0 top
NOREF#1851  -  []  167.7 136.27 90 top
NOREF#1852  -  []  309.51 253.69 0 top
NOREF#1853  -  []  263.83 231.63 90 top
NOREF#1854  -  []  411.26 163.19 90 top
NOREF#1855  -  []  118.99 171.65 0 top
NOREF#1856  -  []  332.51 205.56 90 top
NOREF#1857  -  []  405.93 288.67 90 top
NOREF#1858  -  []  124.35 187.53 0 top
NOREF#1859  -  []  415.6 146.88 0 top
NOREF#1860  -  []  100.73 238.84 0 top
NOREF#1861  -  []  412.62 249.11 0 top
NOREF#1862  -  []  375.73 199.18 90 top
NOREF#1863  -  []  398.65 265.37 0 top
NOREF#1864  -  []  396.55 257.37 0 top
NOREF#1865  -  []  410.78 131.89 0 top
NOREF#1866  -  []  313.77 146.05 90 top
NOREF#1867  -  []  451.68 171.53 0 top
NOREF#1868  -  []  251.33 140.14 0 top
NOREF#1869  -  []  328.33 187.93 0 top
NOREF#1870  -  []  352.25 244.86 90 top
NOREF#1871  -  []  182.57 254 90 top
NOREF#1872  -  []  390.69 289.12 0 top
NOREF#1873  -  []  417.2 163.64 0 top
NOREF#1874  -  []  175.7 154.88 90 top
NOREF#1875  -  []  392.47 288.57 90 top
NOREF#1876  -  []  106.03 217.88 90 top
NOREF#1877  -  []  392.47 224.4 90 top
NOREF#1878  -  []  194.09 160.4 90 top
NOREF#1879  -  []  167.7 231.27 90 top
NOREF#1880  -  []  310.43 187.61 0 top
NOREF#1881  -  []  478.57 277.31 90 top
NOREF#1882  -  []  468.68 129.54 0 top
NOREF#1883  -  []  448.94 290.38 90 top
NOREF#1884  -  []  352.25 242.32 90 top
NOREF#1885  -  []  192.57 215.25 90 top
NOREF#1886  -  []  341.63 173.83 90 top
NOREF#1887  -  []  116.27 171.02 0 top
NOREF#1888  -  []  343.2 172.26 90 top
NOREF#1889  -  []  122.15 187.53 0 top
NOREF#1890  -  []  321.82 227.13 90 top
NOREF#1891  -  []  250.49 163.52 90 top
NOREF#1892  -  []  450.03 191.31 0 top
NOREF#1893  -  []  460.89 174.46 90 top
NOREF#1894  -  []  247.25 265.56 0 top
NOREF#1895  -  []  413.51 207.71 90 top
NOREF#1896  -  []  401.52 210.88 90 top
NOREF#1897  -  []  175.7 222.95 90 top
NOREF#1898  -  []  165.8 158.5 0 top
NOREF#1899  -  []  247.57 265.86 90 top
NOREF#1900  -  []  327.89 264.35 90 top
NOREF#1901  -  []  249.85 224.72 0 top
NOREF#1902  -  []  352.25 241.69 0 top
NOREF#1903  -  []  230.43 188.88 90 top
NOREF#1904  -  []  238.3 288.61 0 top
NOREF#1905  -  []  215.96 177.06 0 top
NOREF#1906  -  []  343.63 225.04 90 top
NOREF#1907  -  []  166.06 230.19 90 top
NOREF#1908  -  []  327.57 265.86 90 top
NOREF#1909  -  []  199.33 212.85 90 top
NOREF#1910  -  []  346.27 129.42 90 top
NOREF#1911  -  []  304.82 146.05 0 top
NOREF#1912  -  []  380.59 239.21 0 top
NOREF#1913  -  []  106.36 190.55 0 top
NOREF#1914  -  []  263.95 223.52 90 top
NOREF#1915  -  []  226.27 216.63 90 top
NOREF#1916  -  []  168.13 132.17 90 top
NOREF#1917  -  []  518.38 257.36 90 top
NOREF#1918  -  []  332.61 296.86 0 top
NOREF#1919  -  []  66.26 271.33 90 top
NOREF#1920  -  []  351.34 241.37 0 top
NOREF#1921  -  []  192.57 256.4 90 top
NOREF#1922  -  []  182.57 171.96 90 top
NOREF#1923  -  []  253.4 205.56 90 top
NOREF#1924  -  []  330.74 224.74 0 top
NOREF#1925  -  []  390.69 257.11 0 top
NOREF#1926  -  []  216.96 240.71 0 top
NOREF#1927  -  []  405.93 256.92 90 top
NOREF#1928  -  []  495.08 257.36 90 top
NOREF#1929  -  []  11.6 261.68 90 top
NOREF#1930  -  []  175.8 174.36 90 top
NOREF#1931  -  []  351.34 183.91 0 top
NOREF#1932  -  []  420.15 131.44 90 top
NOREF#1933  -  []  383.07 180.2 90 top
NOREF#1934  -  []  396.55 273.11 0 top
NOREF#1935  -  []  295.96 177.06 0 top
NOREF#1936  -  []  272.25 244.23 0 top
NOREF#1937  -  []  167.7 200.54 90 top
NOREF#1938  -  []  405.51 217.61 0 top
NOREF#1939  -  []  168.13 240.88 90 top
NOREF#1940  -  []  167.7 258.7 90 top
NOREF#1941  -  []  127.55 184.33 90 top
NOREF#1942  -  []  247.25 264.35 90 top
NOREF#1943  -  []  352.25 181.05 90 top
NOREF#1944  -  []  119.95 187.53 0 top
NOREF#1945  -  []  373.73 207.21 0 top
NOREF#1946  -  []  249.28 165.04 90 top
NOREF#1947  -  []  177.33 214.75 90 top
NOREF#1948  -  []  311.44 288.86 0 top
NOREF#1949  -  []  209.59 160.9 90 top
NOREF#1950  -  []  334.29 204.35 90 top
NOREF#1951  -  []  167.7 187.92 90 top
NOREF#1952  -  []  310.73 186.66 0 top
NOREF#1953  -  []  118.96 179.19 0 top
NOREF#1954  -  []  217.41 273.24 90 top
NOREF#1955  -  []  271.04 249.18 0 top
NOREF#1956  -  []  420.62 239.21 90 top
NOREF#1957  -  []  172.08 289.11 90 top
NOREF#1958  -  []  400.85 265.37 0 top
NOREF#1959  -  []  395.2 249.11 0 top
NOREF#1960  -  []  36.1 131.91 0 top
NOREF#1961  -  []  110.47 171.02 0 top
NOREF#1962  -  []  96.33 238.84 0 top
NOREF#1963  -  []  259.33 265.56 90 top
NOREF#1964  -  []  337.9 186.99 0 top
NOREF#1965  -  []  184.47 244.98 90 top
NOREF#1966  -  []  192.47 202.99 90 top
NOREF#1967  -  []  305.83 264.31 0 top
NOREF#1968  -  []  230.43 246.34 0 top
NOREF#1969  -  []  401.87 139.89 0 top
NOREF#1970  -  []  118.7 195.7 0 top
NOREF#1971  -  []  397.8 163.09 90 top
NOREF#1972  -  []  192.47 168.6 90 top
NOREF#1973  -  []  199.08 254 0 top
NOREF#1974  -  []  271.34 242.64 0 top
NOREF#1975  -  []  247.25 205.55 0 top
NOREF#1976  -  []  184.47 174.46 90 top
NOREF#1977  -  []  406.44 154.88 0 top
NOREF#1978  -  []  289.29 296.86 0 top
NOREF#1979  -  []  463.61 179.15 0 top
NOREF#1980  -  []  215.96 237.06 0 top
NOREF#1981  -  []  375.73 193.43 90 top
NOREF#1982  -  []  302.11 240.71 0 top
NOREF#1983  -  []  253.53 140.14 0 top
NOREF#1984  -  []  118.33 289.48 90 top
NOREF#1985  -  []  331.54 192.73 90 top
NOREF#1986  -  []  383.09 224.85 0 top
NOREF#1987  -  []  201.23 186.57 0 top
NOREF#1988  -  []  253.72 204.65 90 top
NOREF#1989  -  []  375.73 196.98 90 top
NOREF#1990  -  []  477.24 239.09 0 top
NOREF#1991  -  []  182.57 212.85 90 top
NOREF#1992  -  []  334.61 265.86 90 top
NOREF#1993  -  []  371.48 265.11 0 top
NOREF#1994  -  []  107.02 171.57 0 top
NOREF#1995  -  []  118.33 273.87 90 top
NOREF#1996  -  []  271.34 245.18 0 top
NOREF#1997  -  []  326.43 288.31 90 top
NOREF#1998  -  []  448.94 292.92 90 top
NOREF#1999  -  []  379.48 239.21 90 top
NOREF#2000  -  []  459.24 175.86 90 top
NOREF#2001  -  []  385.61 208.66 90 top
NOREF#2002  -  []  382.82 180.15 0 top
NOREF#2003  -  []  263.63 163.82 90 top
NOREF#2004  -  []  309.51 189.2 0 top
NOREF#2005  -  []  209.23 232.37 90 top
NOREF#2006  -  []  251.94 204.65 90 top
NOREF#2007  -  []  318.32 131.64 0 top
NOREF#2008  -  []  127.59 211.59 90 top
NOREF#2009  -  []  209.49 177.76 90 top
NOREF#2010  -  []  192.57 187.82 90 top
NOREF#2011  -  []  453.88 214.96 0 top
NOREF#2012  -  []  330.74 224.72 0 top
NOREF#2013  -  []  331.94 204.65 90 top
NOREF#2014  -  []  342.04 164.74 0 top
NOREF#2015  -  []  450.03 225.6 0 top
NOREF#2016  -  []  272.25 249.82 0 top
NOREF#2017  -  []  284.36 280.1 0 top
NOREF#2018  -  []  249.85 164.72 0 top
NOREF#2019  -  []  201.23 227.72 90 top
NOREF#2020  -  []  384.08 209.16 90 top
NOREF#2021  -  []  184.47 258.7 90 top
NOREF#2022  -  []  386.46 139.89 0 top
NOREF#2023  -  []  341.63 233.83 90 top
NOREF#2024  -  []  316.97 139.64 0 top
NOREF#2025  -  []  336.45 224.72 0 top
NOREF#2026  -  []  329.85 164.72 0 top
NOREF#2027  -  []  118.7 217.73 90 top
NOREF#2028  -  []  271.04 182.96 0 top
NOREF#2029  -  []  343.95 223.52 90 top
NOREF#2030  -  []  66.26 273.87 90 top
NOREF#2031  -  []  394.46 129.99 90 top
NOREF#2032  -  []  459.28 192.71 0 top
NOREF#2033  -  []  415.1 163.64 0 top
NOREF#2034  -  []  201.23 214 90 top
NOREF#2035  -  []  448.94 273.87 90 top
NOREF#2036  -  []  192.47 230.17 90 top
NOREF#2037  -  []  278.6 147.38 0 top
NOREF#2038  -  []  451.68 195.91 0 top
NOREF#2039  -  []  377.23 273.11 0 top
NOREF#2040  -  []  209.23 195.52 90 top
NOREF#2041  -  []  217.41 213.24 0 top
NOREF#2042  -  []  261.21 286.96 0 top
NOREF#2043  -  []  384.36 131.89 0 top
NOREF#2044  -  []  272.25 181.05 90 top
NOREF#2045  -  []  250.23 132.14 0 top
NOREF#2046  -  []  247.34 133.41 90 top
NOREF#2047  -  []  461.86 230.75 0 top
NOREF#2048  -  []  354.27 134.07 90 top
NOREF#2049  -  []  394.05 271.21 0 top
NOREF#2050  -  []  478.57 259.9 90 top
NOREF#2051  -  []  383.09 289.12 0 top
NOREF#2052  -  []  253.4 265.55 0 top
NOREF#2053  -  []  407.71 217.61 0 top
NOREF#2054  -  []  257.09 223.52 90 top
NOREF#2055  -  []  390.59 195.9 90 top
NOREF#2056  -  []  184.47 186.57 90 top
NOREF#2057  -  []  259.65 264.65 90 top
NOREF#2058  -  []  298.16 177.06 0 top
NOREF#2059  -  []  201.23 190.12 90 top
NOREF#2060  -  []  111.54 290.38 90 top
NOREF#2061  -  []  392.04 273.11 90 top
NOREF#2062  -  []  448.94 276.41 90 top
NOREF#2063  -  []  406.65 255.47 90 top
NOREF#2064  -  []  253.4 205.56 0 top
NOREF#2065  -  []  303.56 185.29 90 top
NOREF#2066  -  []  249.6 164.74 90 top
NOREF#2067  -  []  369.38 241.11 0 top
NOREF#2068  -  []  420.88 129.99 90 top
NOREF#2069  -  []  472.86 166.93 90 top
NOREF#2070  -  []  339.33 265.55 0 top
NOREF#2071  -  []  388.43 180.15 0 top
NOREF#2072  -  []  167.7 255.15 0 top
NOREF#2073  -  []  398.53 144.98 90 top
NOREF#2074  -  []  306.85 271.67 0 top
NOREF#2075  -  []  167.7 161 90 top
NOREF#2076  -  []  329.6 224.74 90 top
NOREF#2077  -  []  373.93 281.11 0 top
NOREF#2078  -  []  419.9 240.66 90 top
NOREF#2079  -  []  120.24 171.1 0 top
NOREF#2080  -  []  373.83 192.28 90 top
NOREF#2081  -  []  108.01 214.71 0 top
NOREF#2082  -  []  473.7 176.22 90 top
NOREF#2083  -  []  451.64 222.5 0 top
NOREF#2084  -  []  392.21 131.94 90 top
NOREF#2085  -  []  265.81 288.86 0 top
NOREF#2086  -  []  260.83 234.63 90 top
NOREF#2087  -  []  367.73 274.38 90 top
NOREF#2088  -  []  184.47 201.89 90 top
NOREF#2089  -  []  331.06 163.82 90 top
NOREF#2090  -  []  192.47 259.8 90 top
NOREF#2091  -  []  409.74 163.69 90 top
NOREF#2092  -  []  218.16 177.06 0 top
NOREF#2093  -  []  389.7 209.36 0 top
NOREF#2094  -  []  118.7 188.08 0 top
NOREF#2095  -  []  324.9 288.91 90 top
NOREF#2096  -  []  386.53 148.15 90 top
NOREF#2097  -  []  328.96 224.74 0 top
NOREF#2098  -  []  333.4 205.56 0 top
NOREF#2099  -  []  167.7 174.46 90 top
NOREF#2100  -  []  250.73 205.56 90 top
NOREF#2101  -  []  376.23 209.11 0 top
NOREF#2102  -  []  310.73 243.41 0 top
NOREF#2103  -  []  334.29 265.55 0 top
NOREF#2104  -  []  262.04 164.72 0 top
NOREF#2105  -  []  249.28 225.04 90 top
NOREF#2106  -  []  317.66 224.74 0 top
NOREF#2107  -  []  472.86 217.98 90 top
NOREF#2108  -  []  272.25 184.23 0 top
NOREF#2109  -  []  201.21 290.01 90 top
NOREF#2110  -  []  450.03 210.36 0 top
NOREF#2111  -  []  465.81 214.96 0 top
NOREF#2112  -  []  245.15 288.66 90 top
NOREF#2113  -  []  419.47 289.12 90 top
NOREF#2114  -  []  339.33 264.35 90 top
NOREF#2115  -  []  311.69 288.91 90 top
NOREF#2116  -  []  351.34 189.5 0 top
NOREF#2117  -  []  378.33 224.6 90 top
NOREF#2118  -  []  271.04 241.69 0 top
NOREF#2119  -  []  106.36 190.55 0 top
NOREF#2120  -  []  184.47 233.47 90 top
NOREF#2121  -  []  271.34 241.37 0 top
NOREF#2122  -  []  376.98 224.6 0 top
NOREF#2123  -  []  390.69 224.85 0 top
NOREF#2124  -  []  264.29 272.1 90 top
NOREF#2125  -  []  451.64 222.5 0 top
NOREF#2126  -  []  175.7 177.76 90 top
NOREF#2127  -  []  475.04 195.66 0 top
NOREF#2128  -  []  184.47 145.93 0 top
NOREF#2129  -  []  377.32 188.15 0 top
NOREF#2130  -  []  229.21 188.88 0 top
NOREF#2131  -  []  167.7 217.55 90 top
NOREF#2132  -  []  451.64 179.06 0 top
NOREF#2133  -  []  271.34 189.5 0 top
NOREF#2134  -  []  167.7 163.2 90 top
NOREF#2135  -  []  334.29 205.56 90 top
NOREF#2136  -  []  317.83 257.63 0 top
NOREF#2137  -  []  377.48 289.17 90 top
NOREF#2138  -  []  478.57 274.77 90 top
NOREF#2139  -  []  199.33 185.42 90 top
NOREF#2140  -  []  272.8 145.48 90 top
NOREF#2141  -  []  470.71 183.57 90 top
NOREF#2142  -  []  298.24 288.86 0 top
NOREF#2143  -  []  309.51 249.2 0 top
NOREF#2144  -  []  273.5 148.65 90 top
